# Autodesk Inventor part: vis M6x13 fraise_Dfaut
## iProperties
Created: 2006-03
Part Number: vis M6x13 fraise_Dfaut
Document SubType Name: Modeling
Designer: Flavien MARTY
Author: Flavien MARTY
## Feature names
1. Base1
